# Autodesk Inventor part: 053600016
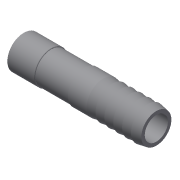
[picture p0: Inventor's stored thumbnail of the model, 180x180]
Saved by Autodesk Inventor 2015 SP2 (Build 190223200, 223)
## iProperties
Created: 2017-10
Part Number: 053600016
Material: Generic
Description: PLASSON HOSE NOZZLE-CEM. PVC 16
Document SubType Name: Modeling
Designer: KIM
Density: 1 g/cm^3
Appearance: Default
Author: KIM
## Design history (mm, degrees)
derived "053600.ipt"
feature "Solid1::053600.ipt"
tag "TaggingFeature1"
body "Solid1"
other parameters: "d0" = 58, "d1" = 170 deg, "d2" = 16, "d4" = 14, "d5" = 16, "d6" = 11.2, "d8" = 23.2, "d9" = 15.36, "d10" = 14.5, "d11" = 0.16, "d14" = 0.16, "d_" = 16, "E_" = 16, "H_" = 58, "L_" = 14
